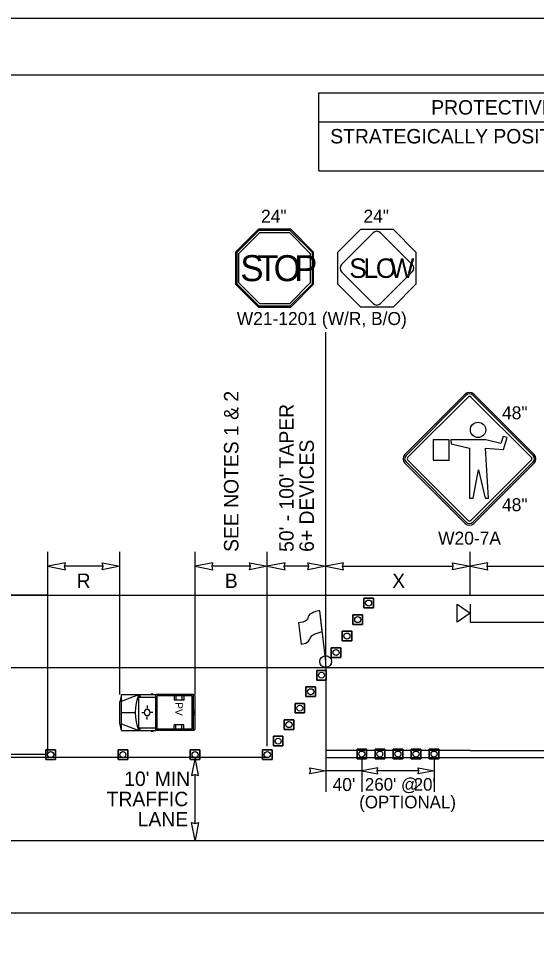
# Model space of a CAD drawing. Extents: x 99999.1 to 100095.7, y 99995 to 100010.7.
# Drawn here: x 100009.77 to 100012.64, y 100005.57 to 100010.69 of the extents above; entities that cross this region are included whole.
import ezdxf

# ---------------------------------------------------------------- set-up
doc = ezdxf.new("R2010")
doc.units = 0
for name, color, linetype in [('RD_ED_ShoulderPavedEdge', 7, 'Continuous'), ('RD_MK_LineDblYellowCenter', 7, 'Continuous'), ('RD_MK_LineEdgeWhite', 7, 'Continuous'), ('RD_MK_LineNoPass', 7, 'Continuous'), ('RD_MK_LineSkipCenter', 7, 'Continuous'), ('SH_GI_PlotLimits', 7, 'Continuous'), ('SH_GI_SheetBorder', 7, 'Continuous'), ('SH_TI_Tables', 7, 'Continuous'), ('TR_SN_ConstructionSigns', 7, 'Continuous'), ('TR_WZ_FlaggingStation', 7, 'Continuous'), ('TR_WZ_PortableSignMountBlk-Org', 7, 'Continuous'), ('TR_WZ_ProtectiveVehicle', 7, 'Continuous'), ('TR_WZ_TrafficCone', 7, 'Continuous'), ('TR_WZ_WorkZoneDetails', 7, 'Continuous'), ('TR_WZ_WorkZoneTextCurrent', 7, 'Continuous')]:
    doc.layers.add(name, color=color, linetype=linetype)

msp = doc.modelspace()

# ---------------------------------------------------------------- linework, layer by layer
at = {"layer": 'RD_ED_ShoulderPavedEdge'}
for p, q in [((100000.1076, 100007.4923), (100015.6424, 100007.4923)), ((100000.1076, 100005.7323), (100015.6424, 100005.7323))]:
    msp.add_line(p, q, dxfattribs=at)
at = {"layer": 'RD_MK_LineDblYellowCenter'}
for p, q in [((100012.2733, 100006.6323), (100015.6631, 100006.6323)), ((100012.2733, 100006.5923), (100015.6218, 100006.5923))]:
    msp.add_line(p, q, dxfattribs=at)
at = {"layer": 'RD_MK_LineEdgeWhite'}
for p, q in [((100000.1076, 100007.0923), (100015.6424, 100007.0923)), ((100000.1076, 100006.1323), (100015.6424, 100006.1323))]:
    msp.add_line(p, q, dxfattribs=at)
at = {"layer": 'RD_MK_LineNoPass'}
msp.add_line((100011.4733, 100006.5923), (100012.2733, 100006.5923), dxfattribs=at)
at = {"layer": 'RD_MK_LineSkipCenter'}
for points in [[(100012.2733, 100006.6323), (100011.4733, 100006.6323)], [(100011.15, 100006.5923), (100003.4767, 100006.5923)]]:
    msp.add_lwpolyline(points, dxfattribs=at)
at = {"layer": 'SH_GI_PlotLimits'}
msp.add_lwpolyline([(99999.0625, 99999.6875), (100016.0625, 99999.6875), (100016.0625, 100010.6875), (99999.0625, 100010.6875)], close=True, dxfattribs=at)
at = {"layer": 'SH_GI_SheetBorder'}
msp.add_line((100000, 100010.375), (100015.75, 100010.375), dxfattribs=at)
at = {"layer": 'SH_TI_Tables'}
for p, q in [((100011.4347, 100009.843), (100011.4347, 100010.275)), ((100011.4347, 100010.275), (100015.65, 100010.275)), ((100011.4347, 100010.115), (100015.65, 100010.115)), ((100011.4347, 100009.843), (100015.65, 100009.843))]:
    msp.add_line(p, q, dxfattribs=at)
at = {"layer": 'TR_SN_ConstructionSigns'}
for p, q in [((100011.1006, 100009.5201), (100010.9741, 100009.3936)), ((100011.1034, 100009.5134), (100010.9809, 100009.3908)), ((100010.9921, 100009.3861), (100011.1081, 100009.5021)), ((100011.2796, 100009.5201), (100011.1006, 100009.5201)), ((100011.2768, 100009.5134), (100011.1034, 100009.5134)), ((100011.1081, 100009.5021), (100011.2721, 100009.5021)), ((100011.2721, 100009.5021), (100011.3881, 100009.3861)), ((100011.3994, 100009.3908), (100011.2768, 100009.5134)), ((100011.4061, 100009.3936), (100011.2796, 100009.5201)), ((100011.7367, 100009.4997), (100011.5615, 100009.3245)), ((100011.9527, 100009.3245), (100011.7775, 100009.4997)), ((100010.9741, 100009.3936), (100010.9741, 100009.2146)), ((100010.9809, 100009.3908), (100010.9809, 100009.2174)), ((100010.9921, 100009.2221), (100010.9921, 100009.3861)), ((100011.3881, 100009.3861), (100011.3881, 100009.2221)), ((100011.3994, 100009.2174), (100011.3994, 100009.3908)), ((100011.4061, 100009.2146), (100011.4061, 100009.3936)), ((100011.5615, 100009.2837), (100011.7367, 100009.1085)), ((100011.7775, 100009.1085), (100011.9527, 100009.2837)), ((100010.9741, 100009.2146), (100011.1006, 100009.0881)), ((100010.9809, 100009.2174), (100011.1034, 100009.0949)), ((100011.1081, 100009.1061), (100010.9921, 100009.2221)), ((100011.3881, 100009.2221), (100011.2721, 100009.1061)), ((100011.2768, 100009.0949), (100011.3994, 100009.2174)), ((100011.2796, 100009.0881), (100011.4061, 100009.2146)), ((100011.1006, 100009.0881), (100011.2796, 100009.0881)), ((100011.1034, 100009.0949), (100011.2768, 100009.0949)), ((100011.2721, 100009.1061), (100011.1081, 100009.1061)), ((100012.2461, 100008.6062), (100011.912, 100008.2721)), ((100012.2521, 100008.6002), (100011.918, 100008.2661)), ((100011.9279, 100008.2561), (100012.262, 100008.5903)), ((100012.2779, 100008.5903), (100012.612, 100008.2561)), ((100012.622, 100008.2661), (100012.2879, 100008.6002)), ((100012.6279, 100008.2721), (100012.2938, 100008.6062)), ((100011.912, 100008.2243), (100012.2461, 100007.8902)), ((100011.918, 100008.2303), (100012.2521, 100007.8962)), ((100012.262, 100007.9061), (100011.9279, 100008.2402)), ((100012.612, 100008.2402), (100012.2779, 100007.9061)), ((100012.2879, 100007.8962), (100012.622, 100008.2303)), ((100012.2938, 100007.8902), (100012.6279, 100008.2243))]:
    msp.add_line(p, q, dxfattribs=at)
for points in [[(100011.9731, 100009.3936), (100011.9731, 100009.2146), (100011.8466, 100009.0881), (100011.6676, 100009.0881), (100011.5411, 100009.2146), (100011.5411, 100009.3936), (100011.6676, 100009.5201), (100011.8466, 100009.5201)], [(100012.1666, 100008.3526), (100012.1679, 100008.3309), (100012.2705, 100008.307), (100012.2705, 100008.0307), (100012.2905, 100008.0307), (100012.3187, 100008.1877), (100012.3562, 100008.0307), (100012.3752, 100008.0307), (100012.3585, 100008.3069), (100012.4588, 100008.2988), (100012.4777, 100008.3658), (100012.457, 100008.3717), (100012.4438, 100008.3334), (100012.3609, 100008.3526)], [(100012.0687, 100008.3523), (100012.0687, 100008.2401), (100012.1563, 100008.2401), (100012.1563, 100008.3523)]]:
    msp.add_lwpolyline(points, close=True, dxfattribs=at)
msp.add_circle((100012.3169, 100008.4081), 0.0424, dxfattribs=at)
for centre, radius, start, end in [((100011.7571, 100009.4794), 0.0288, 45, 135), ((100011.5818, 100009.3041), 0.0288, 135, 225), ((100011.9324, 100009.3041), 0.0288, 315, 45), ((100011.7571, 100009.1288), 0.0288, 225, 315), ((100012.27, 100008.5823), 0.0338, 45, 135), ((100012.27, 100008.5823), 0.0253, 45, 135), ((100012.27, 100008.5823), 0.0113, 45, 135), ((100011.9359, 100008.2482), 0.0338, 135, 225), ((100011.9359, 100008.2482), 0.0253, 135, 225), ((100011.9359, 100008.2482), 0.0113, 135, 225), ((100012.6041, 100008.2482), 0.0113, 315, 45), ((100012.6041, 100008.2482), 0.0253, 315, 45), ((100012.6041, 100008.2482), 0.0338, 315, 45), ((100012.27, 100007.9141), 0.0113, 225, 315), ((100012.27, 100007.9141), 0.0338, 225, 315), ((100012.27, 100007.9141), 0.0253, 225, 315)]:
    msp.add_arc(centre, radius, start, end, dxfattribs=at)
at = {"layer": 'TR_WZ_FlaggingStation'}
for p, q in [((100011.4543, 100007.2917), (100011.4413, 100007.4061)), ((100011.4733, 100007.1248), (100011.4413, 100007.4058)), ((100011.3233, 100007.3383), (100011.3366, 100007.2211)), ((100011.4543, 100007.2917), (100011.4543, 100007.2917))]:
    msp.add_line(p, q, dxfattribs=at)
for points in [[(100011.4413, 100007.4061), (100011.4355, 100007.4048), (100011.4177, 100007.4014), (100011.4039, 100007.3972), (100011.3942, 100007.3911), (100011.3857, 100007.3864), (100011.38, 100007.3796), (100011.3757, 100007.3717), (100011.3752, 100007.3655), (100011.3698, 100007.3563), (100011.359, 100007.3489), (100011.3466, 100007.3437), (100011.3233, 100007.3383)], [(100011.3366, 100007.2211), (100011.3448, 100007.2225), (100011.3624, 100007.2271), (100011.3781, 100007.2376), (100011.3846, 100007.2482), (100011.3885, 100007.2585), (100011.3976, 100007.2694), (100011.4086, 100007.2756), (100011.4259, 100007.2827), (100011.4543, 100007.2917)]]:
    msp.add_lwpolyline(points, dxfattribs=at)
msp.add_circle((100011.4733, 100007.1248), 0.0325, dxfattribs=at)
at = {"layer": 'TR_WZ_PortableSignMountBlk-Org'}
msp.add_line((100012.2733, 100007.4422), (100012.2733, 100007.3422), dxfattribs=at)
msp.add_lwpolyline([(100012.2733, 100007.3923), (100012.2015, 100007.3422), (100012.2015, 100007.4422)], close=True, dxfattribs=at)
at = {"layer": 'TR_WZ_ProtectiveVehicle'}
for p, q in [((100010.343, 100006.9423), (100010.3338, 100006.902)), ((100010.343, 100006.7423), (100010.343, 100006.9423)), ((100010.343, 100006.9423), (100010.5319, 100006.9423)), ((100010.343, 100006.9057), (100010.4375, 100006.9423)), ((100010.4375, 100006.7423), (100010.4375, 100006.9423)), ((100010.4392, 100006.7423), (100010.4392, 100006.9423)), ((100010.4492, 100006.9268), (100010.4392, 100006.9423)), ((100010.4392, 100006.9268), (100010.5319, 100006.9268)), ((100010.5062, 100006.9451), (100010.5175, 100006.9451)), ((100010.5319, 100006.7423), (100010.5319, 100006.9423)), ((100010.7404, 100006.9423), (100010.5347, 100006.9423)), ((100010.5347, 100006.7423), (100010.5347, 100006.9423)), ((100010.7346, 100006.9344), (100010.5405, 100006.9344)), ((100010.5405, 100006.7503), (100010.5405, 100006.9344)), ((100010.6332, 100006.9344), (100010.6332, 100006.9113)), ((100010.6432, 100006.9344), (100010.6432, 100006.9113)), ((100010.6772, 100006.9344), (100010.6772, 100006.9113)), ((100010.6882, 100006.9344), (100010.6882, 100006.9113)), ((100010.7346, 100006.7503), (100010.7346, 100006.9344)), ((100010.7404, 100006.7423), (100010.7404, 100006.9423)), ((100010.7456, 100006.939), (100010.7411, 100006.939)), ((100010.7411, 100006.7456), (100010.7411, 100006.939)), ((100010.75, 100006.7517), (100010.75, 100006.9329)), ((100010.3338, 100006.7827), (100010.3338, 100006.902)), ((100010.4852, 100006.8808), (100010.485, 100006.8658)), ((100010.6882, 100006.9113), (100010.6332, 100006.9113)), ((100010.343, 100006.8423), (100010.4189, 100006.8423)), ((100010.4544, 100006.8422), (100010.467, 100006.8423)), ((100010.4986, 100006.8427), (100010.4986, 100006.8427)), ((100010.5154, 100006.8431), (100010.5005, 100006.8427)), ((100010.75, 100006.8564), (100010.7411, 100006.8527)), ((100010.75, 100006.8282), (100010.7411, 100006.832)), ((100010.7476, 100006.8423), (100010.7435, 100006.8423)), ((100010.7456, 100006.8395), (100010.7456, 100006.8451)), ((100010.343, 100006.7423), (100010.3338, 100006.7827)), ((100010.343, 100006.779), (100010.4375, 100006.7423)), ((100010.4845, 100006.8027), (100010.4845, 100006.8188)), ((100010.6882, 100006.7733), (100010.6332, 100006.7733)), ((100010.6332, 100006.7503), (100010.6332, 100006.7733)), ((100010.6432, 100006.7503), (100010.6432, 100006.7733)), ((100010.6772, 100006.7503), (100010.6772, 100006.7733)), ((100010.6882, 100006.7503), (100010.6882, 100006.7733)), ((100010.343, 100006.7423), (100010.5319, 100006.7423)), ((100010.4392, 100006.7423), (100010.4512, 100006.7578)), ((100010.4392, 100006.7578), (100010.5319, 100006.7578)), ((100010.5062, 100006.7395), (100010.5175, 100006.7395)), ((100010.7404, 100006.7423), (100010.5347, 100006.7423)), ((100010.7346, 100006.7503), (100010.5405, 100006.7503)), ((100010.7456, 100006.7456), (100010.7411, 100006.7456))]:
    msp.add_line(p, q, dxfattribs=at)
for centre, major_axis, start_param, end_param in [((100010.5725, 100006.8424), (0, -0.2099), 4.215852, 5.209111), ((100010.7456, 100006.9329), (0, 0.0061), 4.712389, 6.283185), ((100010.7456, 100006.7517), (0, -0.0061), 6.283185, 7.853982)]:
    msp.add_ellipse(centre, major_axis=major_axis, ratio=0.73155, start_param=start_param, end_param=end_param, dxfattribs=at)
for centre, major_axis in [((100010.4845, 100006.8423), (0, 0.0193)), ((100010.7456, 100006.8423), (0, 0.00282))]:
    msp.add_ellipse(centre, major_axis=major_axis, ratio=0.73155, dxfattribs=at)
at = {"layer": 'TR_WZ_TrafficCone'}
for points in [[(100011.6843, 100007.4753), (100011.7376, 100007.4753), (100011.7376, 100007.422), (100011.6843, 100007.422), (100011.6843, 100007.4753)], [(100011.6843, 100007.422), (100011.7376, 100007.422), (100011.7376, 100007.4753), (100011.6843, 100007.4753), (100011.6843, 100007.422)], [(100011.6243, 100007.384), (100011.6776, 100007.384), (100011.6776, 100007.3306), (100011.6243, 100007.3306), (100011.6243, 100007.384)], [(100011.6243, 100007.3306), (100011.6776, 100007.3306), (100011.6776, 100007.384), (100011.6243, 100007.384), (100011.6243, 100007.3306)], [(100011.5643, 100007.2926), (100011.6176, 100007.2926), (100011.6176, 100007.2393), (100011.5643, 100007.2393), (100011.5643, 100007.2926)], [(100011.5643, 100007.2393), (100011.6176, 100007.2393), (100011.6176, 100007.2926), (100011.5643, 100007.2926), (100011.5643, 100007.2393)], [(100011.5043, 100007.2013), (100011.5576, 100007.2013), (100011.5576, 100007.148), (100011.5043, 100007.148), (100011.5043, 100007.2013)], [(100011.5043, 100007.148), (100011.5576, 100007.148), (100011.5576, 100007.2013), (100011.5043, 100007.2013), (100011.5043, 100007.148)], [(100011.4766, 100007.0757), (100011.4233, 100007.0757), (100011.4233, 100007.0224), (100011.4766, 100007.0224), (100011.4766, 100007.0757)], [(100011.4766, 100007.0224), (100011.4233, 100007.0224), (100011.4233, 100007.0757), (100011.4766, 100007.0757), (100011.4766, 100007.0224)], [(100011.4166, 100006.9844), (100011.3633, 100006.9844), (100011.3633, 100006.9311), (100011.4166, 100006.9311), (100011.4166, 100006.9844)], [(100011.4166, 100006.9311), (100011.3633, 100006.9311), (100011.3633, 100006.9844), (100011.4166, 100006.9844), (100011.4166, 100006.9311)], [(100011.3566, 100006.8931), (100011.3033, 100006.8931), (100011.3033, 100006.8397), (100011.3566, 100006.8397), (100011.3566, 100006.8931)], [(100011.3566, 100006.8397), (100011.3033, 100006.8397), (100011.3033, 100006.8931), (100011.3566, 100006.8931), (100011.3566, 100006.8397)], [(100011.2966, 100006.8017), (100011.2433, 100006.8017), (100011.2433, 100006.7484), (100011.2966, 100006.7484), (100011.2966, 100006.8017)], [(100011.2966, 100006.7484), (100011.2433, 100006.7484), (100011.2433, 100006.8017), (100011.2966, 100006.8017), (100011.2966, 100006.7484)], [(100011.2366, 100006.7104), (100011.1833, 100006.7104), (100011.1833, 100006.6571), (100011.2366, 100006.6571), (100011.2366, 100006.7104)], [(100011.2366, 100006.6571), (100011.1833, 100006.6571), (100011.1833, 100006.7104), (100011.2366, 100006.7104), (100011.2366, 100006.6571)], [(100009.9234, 100006.6357), (100009.9767, 100006.6357), (100009.9767, 100006.5823), (100009.9234, 100006.5823), (100009.9234, 100006.6357)], [(100009.9234, 100006.5823), (100009.9767, 100006.5823), (100009.9767, 100006.6357), (100009.9234, 100006.6357), (100009.9234, 100006.5823)], [(100010.3234, 100006.6357), (100010.3767, 100006.6357), (100010.3767, 100006.5823), (100010.3234, 100006.5823), (100010.3234, 100006.6357)], [(100010.3234, 100006.5823), (100010.3767, 100006.5823), (100010.3767, 100006.6357), (100010.3234, 100006.6357), (100010.3234, 100006.5823)], [(100010.7234, 100006.6357), (100010.7767, 100006.6357), (100010.7767, 100006.5823), (100010.7234, 100006.5823), (100010.7234, 100006.6357)], [(100010.7234, 100006.5823), (100010.7767, 100006.5823), (100010.7767, 100006.6357), (100010.7234, 100006.6357), (100010.7234, 100006.5823)], [(100011.1766, 100006.6357), (100011.1233, 100006.6357), (100011.1233, 100006.5823), (100011.1766, 100006.5823), (100011.1766, 100006.6357)], [(100011.1766, 100006.5823), (100011.1233, 100006.5823), (100011.1233, 100006.6357), (100011.1766, 100006.6357), (100011.1766, 100006.5823)], [(100011.7, 100006.639), (100011.6467, 100006.639), (100011.6467, 100006.5857), (100011.7, 100006.5857), (100011.7, 100006.639)], [(100011.7, 100006.5857), (100011.6467, 100006.5857), (100011.6467, 100006.639), (100011.7, 100006.639), (100011.7, 100006.5857)], [(100011.8, 100006.639), (100011.7467, 100006.639), (100011.7467, 100006.5857), (100011.8, 100006.5857), (100011.8, 100006.639)], [(100011.8, 100006.5857), (100011.7467, 100006.5857), (100011.7467, 100006.639), (100011.8, 100006.639), (100011.8, 100006.5857)], [(100011.9, 100006.639), (100011.8467, 100006.639), (100011.8467, 100006.5857), (100011.9, 100006.5857), (100011.9, 100006.639)], [(100011.9, 100006.5857), (100011.8467, 100006.5857), (100011.8467, 100006.639), (100011.9, 100006.639), (100011.9, 100006.5857)], [(100012, 100006.639), (100011.9467, 100006.639), (100011.9467, 100006.5857), (100012, 100006.5857), (100012, 100006.639)], [(100012, 100006.5857), (100011.9467, 100006.5857), (100011.9467, 100006.639), (100012, 100006.639), (100012, 100006.5857)], [(100012.1, 100006.639), (100012.0467, 100006.639), (100012.0467, 100006.5857), (100012.1, 100006.5857), (100012.1, 100006.639)], [(100012.1, 100006.5857), (100012.0467, 100006.5857), (100012.0467, 100006.639), (100012.1, 100006.639), (100012.1, 100006.5857)]]:
    msp.add_lwpolyline(points, dxfattribs=at)
for centre in [(100011.7109, 100007.4486), (100011.6509, 100007.3573), (100011.5909, 100007.266), (100011.5309, 100007.1746), (100011.45, 100007.0491), (100011.39, 100006.9577), (100011.33, 100006.8664), (100011.27, 100006.7751), (100011.21, 100006.6837), (100009.95, 100006.609), (100010.35, 100006.609), (100010.75, 100006.609), (100011.15, 100006.609), (100011.6733, 100006.6123), (100011.7733, 100006.6123), (100011.8733, 100006.6123), (100011.9733, 100006.6123), (100012.0733, 100006.6123)]:
    msp.add_circle(centre, 0.0167, dxfattribs=at)
at = {"layer": 'TR_WZ_WorkZoneDetails'}
for p, q in [((100011.4733, 100007.0923), (100011.4733, 100008.9491)), ((100009.9338, 100007.4923), (100009.9338, 100007.7323)), ((100010.3338, 100006.9423), (100010.3338, 100007.7323)), ((100010.75, 100006.9423), (100010.75, 100007.7323)), ((100011.15, 100006.6557), (100011.15, 100007.7323)), ((100012.2733, 100007.4923), (100012.2733, 100007.7323)), ((100010.24, 100007.6523), (100010.0275, 100007.6523)), ((100011.0563, 100007.6523), (100010.8437, 100007.6523)), ((100011.3796, 100007.6523), (100011.2437, 100007.6523)), ((100011.5671, 100007.6523), (100012.1796, 100007.6523)), ((100012.3671, 100007.6523), (100012.9796, 100007.6523)), ((100012.2733, 100007.3422), (100014.6733, 100007.3422)), ((100011.4733, 100007.0923), (100011.4733, 100006.4023)), ((100011.6733, 100006.5857), (100011.6733, 100006.4023)), ((100012.0733, 100006.5857), (100012.0733, 100006.4023)), ((100011.6733, 100006.5193), (100011.4733, 100006.5193)), ((100011.989, 100006.5193), (100011.7577, 100006.5193)), ((100010.75, 100006.2278), (100010.75, 100006.4986))]:
    msp.add_line(p, q, dxfattribs=at)
for points in [[(100009.9338, 100007.6523), (100010.032, 100007.6331), (100010.0275, 100007.6523), (100010.032, 100007.6716)], [(100010.3338, 100007.6523), (100010.2355, 100007.6331), (100010.24, 100007.6523), (100010.2355, 100007.6716)], [(100010.75, 100007.6523), (100010.8483, 100007.6331), (100010.8437, 100007.6523), (100010.8483, 100007.6716)], [(100011.15, 100007.6523), (100011.0517, 100007.6331), (100011.0563, 100007.6523), (100011.0517, 100007.6716)], [(100011.15, 100007.6523), (100011.2483, 100007.6331), (100011.2437, 100007.6523), (100011.2483, 100007.6716)], [(100011.4733, 100007.6523), (100011.3751, 100007.6331), (100011.3796, 100007.6523), (100011.3751, 100007.6716)], [(100011.4733, 100007.6523), (100011.5716, 100007.6331), (100011.5671, 100007.6523), (100011.5716, 100007.6716)], [(100012.2733, 100007.6523), (100012.1751, 100007.6331), (100012.1796, 100007.6523), (100012.1751, 100007.6716)], [(100012.2733, 100007.6523), (100012.3716, 100007.6331), (100012.3671, 100007.6523), (100012.3716, 100007.6716)], [(100005.15, 100007.4923), (100005.15, 100006.6123), (100009.9338, 100006.6123), (100009.9338, 100007.4923)], [(100010.75, 100006.5923), (100010.7307, 100006.4941), (100010.75, 100006.4986), (100010.7692, 100006.4941)], [(100011.4733, 100006.5193), (100011.3849, 100006.502), (100011.389, 100006.5193), (100011.3849, 100006.5367)], [(100011.6733, 100006.5193), (100011.7618, 100006.502), (100011.7577, 100006.5193), (100011.7618, 100006.5367)], [(100012.0733, 100006.5193), (100011.9849, 100006.502), (100011.989, 100006.5193), (100011.9849, 100006.5367)], [(100010.75, 100006.1341), (100010.7307, 100006.2324), (100010.75, 100006.2278), (100010.7692, 100006.2324)]]:
    msp.add_lwpolyline(points, close=True, dxfattribs=at)

# ---------------------------------------------------------------- texts
at = {"layer": 'SH_TI_Tables'}
for s, p in [('PROTECTIVE VEHICLE ROLL AHEAD DISTANCE = R', (100012.0577, 100010.155)), ('STRATEGICALLY POSITION WORK VEHICLE TO PROTECT WORK CREW.', (100011.4984, 100009.995))]:
    msp.add_text(s, height=0.08, rotation=360, dxfattribs=at).set_placement(p)
at = {"layer": 'TR_SN_ConstructionSigns'}
for s, height, p in [('24"', 0.072, (100011.1154, 100009.5561)), ('24"', 0.072, (100011.6824, 100009.5561)), ('S', 0.144, (100011.0007, 100009.2321)), ('T', 0.144, (100011.0943, 100009.2321)), ('O', 0.144, (100011.1851, 100009.2321)), ('P', 0.144, (100011.2988, 100009.2321)), ('S', 0.108, (100011.6043, 100009.2501)), ('L', 0.108, (100011.6831, 100009.2501)), ('O', 0.108, (100011.7512, 100009.2501)), ('W', 0.108, (100011.8279, 100009.2501))]:
    msp.add_text(s, height=height, dxfattribs=at).set_placement(p)
for s, p in [('W21-1201 (W/R, B/O)', (100010.9809, 100008.9891)), ('48"', (100012.4498, 100008.4667)), ('48"', (100012.4498, 100007.9576)), ('W20-7A', (100012.096, 100007.7723))]:
    msp.add_text(s, height=0.072, rotation=360, dxfattribs=at).set_placement(p)
at = {"layer": 'TR_WZ_ProtectiveVehicle'}
msp.add_text('PV', height=0.04175, rotation=270, dxfattribs=at).set_placement((100010.6398, 100006.899))
at = {"layer": 'TR_WZ_WorkZoneTextCurrent'}
for s, p in [('SEE NOTES 1 & 2', (100010.99, 100007.7323)), ("50' - 100' TAPER", (100011.2957, 100007.7323)), ('6+ DEVICES', (100011.4077, 100007.7323))]:
    msp.add_text(s, height=0.08, rotation=90, dxfattribs=at).set_placement(p)
for s, height, p in [('R', 0.08, (100010.0939, 100007.5323)), ('B', 0.08, (100010.9145, 100007.5323)), ('X', 0.08, (100011.8416, 100007.5323)), ("10' MIN", 0.08, (100010.3575, 100006.4352)), ("40'", 0.072, (100011.5114, 100006.4073)), ("260' @", 0.07, (100011.6903, 100006.4093)), ("20'", 0.07, (100011.9604, 100006.4093)), ('TRAFFIC', 0.08, (100010.2603, 100006.3232)), ('(OPTIONAL)', 0.07, (100011.659, 100006.3113)), ('LANE', 0.08, (100010.4322, 100006.2112))]:
    msp.add_text(s, height=height, dxfattribs=at).set_placement(p)

doc.saveas('drawing.dxf')
